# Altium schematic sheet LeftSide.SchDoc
size A4; SheetNumber: 3; SheetTotal: 3
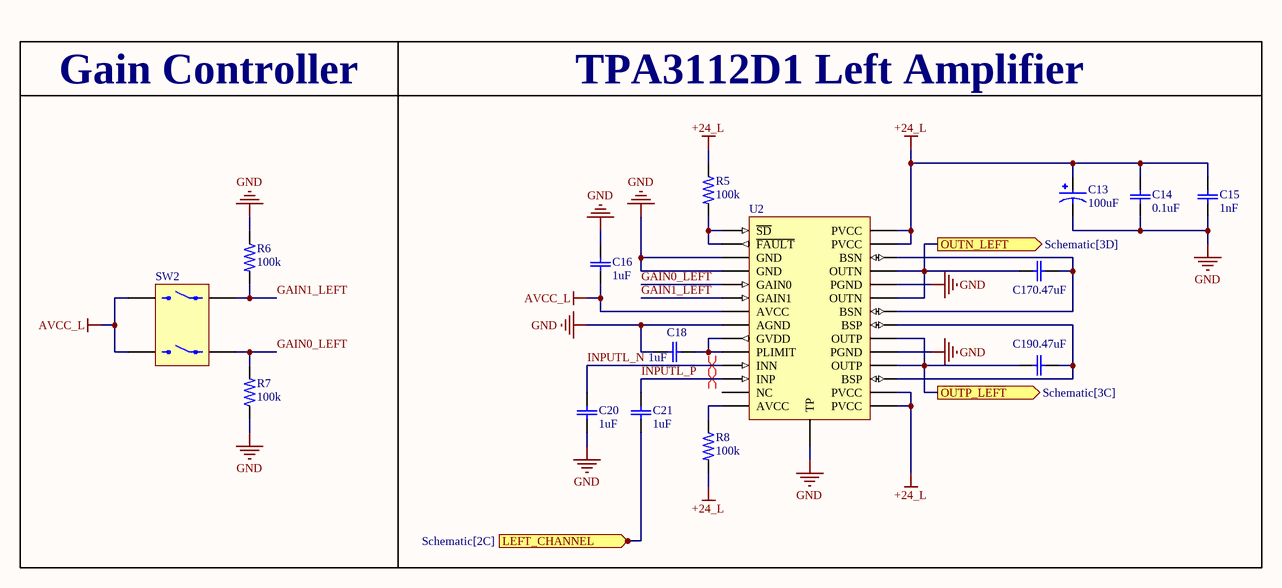
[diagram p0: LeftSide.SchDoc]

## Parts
C13  100uF  [CAPRADIAL_16X10]
C14  0.1uF  [CERAMIC0805]
C15  1nF  [CERAMIC0603]
C16  1uF  [CERAMIC0603]
C17  0.47uF  [CERAMIC0603]
C18  1uF  [CERAMIC0603]
C19  0.47uF  [CERAMIC0603]
C20  1uF  [CERAMIC0603]
C21  1uF  [CERAMIC0603]
R5  100k  [RES0603]
R6  100k  [RES0603]
R7  100k  [RES0603]
R8  100k  [RES0603]
SW2  DIP SWITCH - 2 POS  [KF1001 - 2 POS]  (value not drawn)
U2  TPA3112D1  [HTSSOP-28]  (value not drawn)

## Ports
LEFT_CHANNEL (in, see Schematic[2C]), OUTN_LEFT (out, see Schematic[3D]), OUTP_LEFT (out, see Schematic[3C])

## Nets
+24_L: C13.P C14.2(C2) C15.2(C2) R5.1 R8.2 U2.15(PVCC) U2.16(PVCC) U2.27(PVCC) U2.28(PVCC)
AVCC_L: C16.2(C2) SW2.2 SW2.3 U2.7(AVCC)
GND: C13.N C14.1(C1) C15.1(C1) C16.1(C1) C18.2(C2) C20.1(C1) R6.1 R7.1 U2.3(GND) U2.4(GND) U2.8(AGND) U2.19(PGND) U2.24(PGND) U2.29(TP)
GAIN0_LEFT: R7.2 SW2.1 U2.5(GAIN0)
GAIN1_LEFT: R6.2 SW2.4 U2.6(GAIN1)
INPUTL_N: C20.2(C2) U2.11(INN)
INPUTL_P: C21.2(C2) U2.12(INP)
LEFT_CHANNEL: C21.1(C1) ; port LEFT_CHANNEL
OUTN_LEFT: C17.2(C2) U2.23(OUTN) U2.25(OUTN) ; port OUTN_LEFT
OUTP_LEFT: C19.2(C2) U2.18(OUTP) U2.20(OUTP) ; port OUTP_LEFT
NetC17_1: C17.1(C1) U2.22(BSN) U2.26(BSN)
NetC18_1: C18.1(C1) U2.9(GVDD) U2.10(PLIMIT)
NetC19_1: C19.1(C1) U2.17(BSP) U2.21(BSP)
NetR5_2: R5.2 U2.1(~{SD}) U2.2(~{FAULT})
NetR8_1: R8.1 U2.14(AVCC)

Not connected (* = marked no-connect by the designer): U2 13(NC)

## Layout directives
differential pair: INPUTL_N, INPUTL_P

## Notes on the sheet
- Gain Controller
- TPA3112D1 Left Amplifier

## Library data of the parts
C13 = CAP ELETRO/TANT: MP: EEU-EE2W560; MF: Panasonic
C14-C21 = Cap: MF: KEMET; MP: TAJC226M025RNJ
R5-R8 = RESISTOR SMD: MP: 3-1879460-6
U2 = TPA3112D1: 25W Filter-Free Mono Class-D Audio Power Amplifier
